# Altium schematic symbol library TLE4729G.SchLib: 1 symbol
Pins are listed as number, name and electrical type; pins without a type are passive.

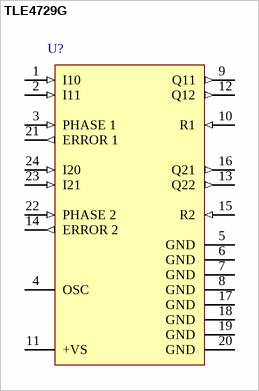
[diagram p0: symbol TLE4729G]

## TLE4729G
designator U?
2-Phase Stepper Motor Driver Bipolar IC, -40 to 150 degC, PG-DSO-24-16, Reel, Green; Manufacturer: Infineon; PartNumber: TLE4729G; Green: TRUE; Inhibit: FALSE; IPeak: 2 x 1 A; Iq: 2 x 0.8 A; Protect: Overtemp. e.a.
footprint INF-PG-DSO-24-16_N (SOP, 24-Leads, Body 15.4x7.5mm, Pitch 1.27mm, IPC Medium Density)
footprint INF-PG-DSO-24-16_L (SOP, 24-Leads, Body 15.4x7.5mm, Pitch 1.27mm, IPC High Density)
footprint INF-PG-DSO-24-16_M (SOP, 24-Leads, Body 15.4x7.5mm, Pitch 1.27mm, IPC Low Density)
pins: 1 I10 (in) "Digital control inputs IX0,IX1 for the magnitude of the current of the particular phase.", 2 I11 (in) "Digital control inputs IX0,IX1 for the magnitude of the current of the particular phase.", 3 PHASE 1 (in) "Input Phase 1; controls the current through phase winding 1. On H-potential the phase current flows from Q11 to Q12, on L-potential in the reverse direction.", 4 OSC "Oscillator; works at approx. 25 kHz if this pin is wired to ground across 2.2 nF.", 5 GND (power) "Ground; all pins are connected internally.", 6 GND (power) "Ground; all pins are connected internally.", 7 GND (power) "Ground; all pins are connected internally.", 8 GND (power) "Ground; all pins are connected internally.", 9 Q11 (out) "Push-pull outputs Q11, Q12 for phase 1 with integrated free-wheeling diodes.", 10 R1 (in) "Resistor R1  for sensing the current in phase 1.", 11 +VS (power) "Supply voltage; block to ground, as close as possible to the IC, with a stable electrolytic capacitor of at least 10 uF in parallel with a ceramic capacitor of 220 nF.", 12 Q12 (out) "Push-pull outputs Q11, Q12 for phase 1 with integrated free-wheeling diodes.", 13 Q22 (out) "Push-pull outputs Q22, Q21 for phase 2 with integrated free-wheeling diodes.", 14 ERROR 2 (out) "Error 2 output; signals with “low” the errors: short circuit to ground of  one or more outputs or over-temperature.", 15 R2 (in) "Resistor R2  for sensing the current in phase 2.", 16 Q21 (out) "Push-pull outputs Q22, Q21 for phase 2 with integrated free-wheeling diodes.", 17 GND (power) "Ground; all pins are connected internally.", 18 GND (power) "Ground; all pins are connected internally.", 19 GND (power) "Ground; all pins are connected internally.", 20 GND (power) "Ground; all pins are connected internally.", 21 ERROR 1 (out) "Error 1 output; signals with “low” the errors: open load or short circuit to  + VS of one or more outputs or short circuit of the load or overtemperature.", 22 PHASE 2 (in) "Input phase 2; controls the current flow through phase winding 2. On H-potential the phase current flows from Q21 to Q22, on L potential in the reverse direction.", 23 I21 (in) "Digital control inputs IX0,IX1 for the magnitude of the current of the particular phase.", 24 I20 (in) "Digital control inputs IX0,IX1 for the magnitude of the current of the particular phase."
